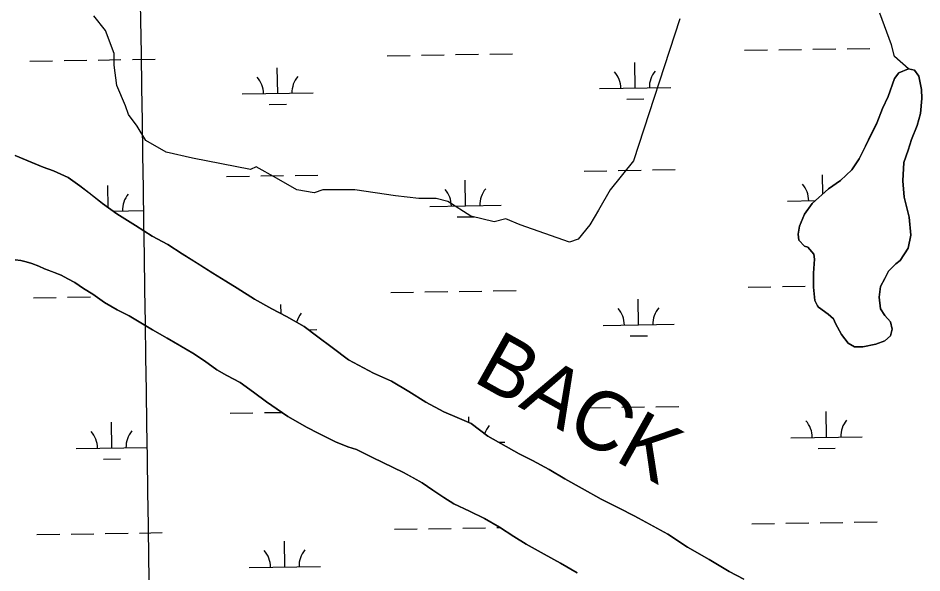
# Model space of a CAD drawing. Extents: x 3807117 to 3845308, y 337856 to 363736.
# Drawn here: x 3826910 to 3828179, y 355901 to 356681 of the extents above; entities that cross this region are included whole.
import ezdxf

# ---------------------------------------------------------------- set-up
doc = ezdxf.new("R2010")
doc.units = 0
for name, color, linetype in [('V-GRID-MAJR', 7, 'Continuous'), ('V-RIVR-IDEN', 7, 'Continuous'), ('V-TOPO-SHOR', 7, 'Continuous'), ('V-WETL-SWMP', 7, 'Continuous')]:
    doc.layers.add(name, color=color, linetype=linetype)

msp = doc.modelspace()

# ---------------------------------------------------------------- linework, layer by layer
at = {"layer": 'V-GRID-MAJR'}
msp.add_spline([(3827279.7490000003, 343519.83400000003), (3827189.006, 349576.481), (3827098.2120000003, 355636.598), (3827007.418, 361696.713), (3827007.366, 361700.18200000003)], degree=3, dxfattribs=at)
at = {"layer": 'V-TOPO-SHOR'}
for points in [[(3827839.4147388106, 356679.8381328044), (3827774.232319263, 356480.2169729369), (3827741.641109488, 356439.47796071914), (3827725.3455046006, 356410.9606521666), (3827713.1238009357, 356390.5911460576), (3827696.8281960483, 356370.2216399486), (3827684.606492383, 356366.14773872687), (3827615.350171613, 356390.5911460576), (3827594.9806655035, 356398.7389485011), (3827578.6850606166, 356394.6650472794), (3827546.0938508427, 356402.81284972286), (3827513.502641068, 356423.18235583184), (3827497.2070361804, 356427.25625705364), (3827472.76362885, 356427.25625705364), (3827440.172419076, 356431.3301582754), (3827383.1378019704, 356439.47796071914), (3827338.324888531, 356439.47796071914), (3827326.1031848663, 356435.40405949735), (3827301.659777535, 356439.47796071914), (3827273.142468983, 356455.7735656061), (3827244.62516043, 356472.0691704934), (3827236.4773579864, 356467.9952692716), (3827154.999333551, 356484.2908741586), (3827118.334222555, 356492.4386766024), (3827089.8169140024, 356508.7342814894), (3827077.5952103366, 356529.1037875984), (3827065.373506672, 356545.3993924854), (3827061.2996054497, 356557.6210961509), (3827049.0779017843, 356586.1384047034), (3827045.0040005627, 356614.65571325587), (3827045.0040005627, 356630.9513181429), (3827032.7822968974, 356663.54252791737), (3827016.48669201, 356683.9120340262)], [(3828160.716, 356609.613), (3828140.883429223, 356626.87741692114), (3828136.809528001, 356643.1730218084), (3828120.5139231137, 356687.9859352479)], [(3828047.919, 356265.02), (3828034.269, 356274.88300000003), (3828032.972, 356276.847), (3828029.098, 356284.04600000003), (3828027.242, 356302.982), (3828027.346, 356322.55700000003), (3828028.758, 356342.125), (3828027.492, 356349.31200000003), (3828019.062, 356359.14400000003), (3828014.501, 356360.47500000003), (3828006.717, 356368.999), (3828005.457, 356377.49), (3828007.475, 356388.574), (3828014.745, 356405.501), (3828025.268, 356420.451), (3828048.22, 356441.21), (3828065.2490000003, 356452.863), (3828080.99, 356467.787), (3828091.5160000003, 356483.39), (3828100.093, 356500.96400000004), (3828108.673, 356518.536), (3828115.931, 356533.507), (3828123.8710000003, 356553.692), (3828131.794, 356570.617), (3828141.068, 356596.016), (3828146.9820000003, 356603.815), (3828160.716, 356609.613), (3828169.191, 356607.61), (3828175.018, 356599.094), (3828178.833, 356580.80100000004), (3828179.415, 356567.74700000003), (3828177.344, 356546.878), (3828172.685, 356529.935), (3828164.7490000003, 356510.401), (3828160.1, 356495.418), (3828154.132, 356477.832), (3828152.688, 356452.39), (3828154.521, 356429.54), (3828161.548, 356401.444), (3828164.022, 356375.981), (3828160.008, 356357.729), (3828148.8170000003, 356340.172), (3828142.921, 356335.635), (3828132.423, 356325.252), (3828127.148, 356314.84), (3828121.214, 356303.777), (3828119.1750000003, 356288.779), (3828121.045, 356272.454), (3828127.52, 356263.286), (3828135.3030000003, 356254.106), (3828137.8540000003, 356243.651), (3828135.196, 356234.532), (3828127.326, 356227.39400000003), (3828114.903, 356222.895), (3828096.612, 356219.077), (3828084.865, 356219.143), (3828075.757, 356224.41000000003), (3828066.686, 356236.207), (3828058.288, 356251.913), (3828055.06, 356258.456), (3828047.919, 356265.02)], [(3826906.341, 356487.853), (3826929.688, 356477.97500000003), (3826945.644, 356471.25800000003), (3826960.048, 356466.109), (3826980.671, 356457.026), (3826996.987, 356445.238), (3827011.747, 356433.847), (3827028.838, 356420.492), (3827049.039, 356405.953), (3827075.0840000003, 356389.43), (3827098.404, 356374.484), (3827120.572, 356362.663), (3827140.784, 356349.68), (3827160.219, 356337.485), (3827183.931, 356322.534), (3827202.199, 356311.127), (3827217.752, 356301.681), (3827242.237, 356285.947), (3827266.347, 356272.555), (3827287.3510000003, 356261.52), (3827311.847, 356247.737), (3827331.27, 356233.2), (3827351.47, 356217.879), (3827374.3910000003, 356200.983), (3827409.3910000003, 356182.072), (3827434.682, 356170.626), (3827458.787, 356156.454), (3827482.886, 356141.112), (3827508.164, 356127.71400000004), (3827526.844, 356119.813), (3827546.3000000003, 356111.125), (3827569.995, 356093.447), (3827613.935, 356068.635), (3827632.6070000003, 356059.174), (3827655.94, 356046.566), (3827678.1010000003, 356033.576), (3827702.208, 356019.795), (3827729.043, 356005.217), (3827754.323, 355992.21), (3827775.328, 355981.565)], [(3826905.9620000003, 356341.21), (3826914.185, 356340.38300000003), (3826921.617, 356338.384), (3826929.436, 356335.992), (3826939.2090000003, 356332.414), (3826947.416, 356328.842), (3826957.58, 356324.871), (3826970.869, 356319.708), (3826980.2430000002, 356314.565), (3826990.006, 356309.42100000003), (3827002.103, 356301.129), (3827014.985, 356292.832), (3827031.375, 356281.386), (3827049.336, 356271.105), (3827066.132, 356262.397), (3827082.532, 356252.906), (3827098.931, 356243.025), (3827119.628, 356231.163), (3827137.198, 356220.884), (3827155.5500000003, 356210.208), (3827171.9420000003, 356199.15), (3827189.11, 356186.916), (3827203.559, 356178.61100000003), (3827221.913, 356168.719), (3827240.642, 356155.30100000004), (3827258.98, 356141.884), (3827272.6380000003, 356132.408), (3827289.028, 356120.962), (3827315.974, 356105.93200000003), (3827331.596, 356097.621), (3827355.815, 356085.347), (3827373.406, 356078.593), (3827385.526, 356074.612), (3827407.794, 356063.52400000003), (3827451.549, 356042.526), (3827462.875, 356036.197), (3827477.714, 356027.891), (3827492.542, 356017.628), (3827508.156, 356007.357), (3827522.2090000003, 355998.666), (3827544.088, 355988.362), (3827565.182, 355977.67100000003), (3827586.271, 355965.80700000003), (3827606.566, 355952.381), (3827623.7430000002, 355941.711), (3827649.128, 355927.864), (3827671.779, 355915.207), (3827695.2060000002, 355901.371)], [(3827775.328, 355981.565), (3827798.663, 355968.957), (3827822.774, 355955.957), (3827850.366, 355937.47500000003), (3827880.6950000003, 355920.14900000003), (3827908.6890000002, 355903.618), (3827929.301, 355892.583)]]:
    msp.add_lwpolyline(points, dxfattribs=at)
at = {"layer": 'V-WETL-SWMP'}
for p, q in [((3827428.6164234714, 356628.1019231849), (3827460.6128323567, 356628.58129977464)), ((3827476.6110367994, 356628.8209880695), (3827508.6074456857, 356629.3003646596)), ((3827524.6056501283, 356629.5400529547), (3827556.6020590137, 356630.0194295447)), ((3827572.6002634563, 356630.25911783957), (3827604.596672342, 356630.7384944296)), ((3827930.4680981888, 356635.6207652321), (3827962.4645070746, 356636.1001418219)), ((3827978.4627115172, 356636.3398301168), (3828010.459120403, 356636.8192067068)), ((3828026.4573248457, 356637.0588950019), (3828058.4537337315, 356637.5382715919)), ((3828074.451938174, 356637.7779598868), (3828106.44834706, 356638.2573364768)), ((3826926.7647487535, 356620.5830811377), (3826958.7611576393, 356621.06245772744)), ((3826974.759362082, 356621.3021460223), (3827006.7557709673, 356621.7815226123)), ((3827022.7539754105, 356622.0212109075), (3827054.750384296, 356622.5005874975)), ((3827070.748588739, 356622.74027579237), (3827102.7449976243, 356623.21965238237)), ((3827776.6535882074, 356582.56859091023), (3827776.11428963, 356618.5645511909)), ((3827274.8019134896, 356575.049748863), (3827274.262614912, 356611.0457091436)), ((3828146.9821931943, 356603.8139728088), (3828141.0671932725, 356596.0159727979)), ((3828160.7171929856, 356609.6129728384), (3828146.9821931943, 356603.8139728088)), ((3828169.1901928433, 356607.6099728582), (3828160.7171929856, 356609.6129728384)), ((3828175.01719273, 356599.09497287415), (3828169.1901928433, 356607.6099728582)), ((3828141.0671932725, 356596.0159727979), (3828131.7941933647, 356570.615972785)), ((3828178.833192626, 356580.8019728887), (3828175.0171927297, 356599.09497287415)), ((3827726.6591993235, 356581.8195649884), (3827826.6479770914, 356583.31761683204)), ((3828179.415192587, 356567.7479728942), (3828178.833192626, 356580.8019728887)), ((3827224.8075246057, 356574.3007229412), (3827324.796302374, 356575.79877478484)), ((3827764.8860992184, 356566.95955626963), (3827788.883405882, 356567.31908871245)), ((3828131.7941933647, 356570.615972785), (3828123.8711934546, 356553.6919727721)), ((3828177.344192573, 356546.8779728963), (3828179.415192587, 356567.7479728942)), ((3827263.0344245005, 356559.44071422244), (3827287.0317311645, 356559.80024666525)), ((3828123.8711934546, 356553.6919727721), (3828115.9311935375, 356533.5059727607)), ((3828172.6851926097, 356529.9359728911), (3828177.3441925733, 356546.8779728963)), ((3828115.9311935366, 356533.5059727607), (3828091.5161938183, 356483.39097272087)), ((3828164.7481926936, 356510.4019728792), (3828172.6851926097, 356529.9359728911)), ((3828160.099192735, 356495.4189728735), (3828164.7481926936, 356510.4019728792)), ((3826945.6442123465, 356471.2579701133), (3826906.340213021, 356487.8519700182)), ((3828154.1311927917, 356477.83197286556), (3828160.099192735, 356495.4189728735)), ((3828091.5161938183, 356483.39097272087), (3828080.9901939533, 356467.7869727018)), ((3828152.688192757, 356452.38997287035), (3828154.1311927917, 356477.83197286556)), ((3826960.047212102, 356466.1099701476), (3826945.6442123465, 356471.2579701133)), ((3826980.6702117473, 356457.0269701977), (3826960.047212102, 356466.1099701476)), ((3827704.983057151, 356466.04985414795), (3827736.979466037, 356466.52923073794)), ((3827752.9776704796, 356466.7689190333), (3827784.974079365, 356467.2482956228)), ((3827800.972283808, 356467.4879839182), (3827832.968692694, 356467.96736050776)), ((3828080.9901939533, 356467.7869727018), (3828065.248194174, 356452.86297267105)), ((3826996.9882114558, 356445.23797023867), (3826980.6702117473, 356457.0269701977)), ((3827203.131382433, 356458.5310121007), (3827235.127791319, 356459.01038869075)), ((3827251.125995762, 356459.2500769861), (3827283.1224046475, 356459.7294535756)), ((3827299.1206090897, 356459.96914187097), (3827331.117017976, 356460.4485184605)), ((3827538.633350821, 356417.1223589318), (3827538.0940522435, 356453.1183192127)), ((3828040.3435145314, 356434.08647829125), (3828039.9457269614, 356460.6371612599)), ((3828065.248194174, 356452.86297267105), (3828048.219194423, 356441.20897263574)), ((3828154.522192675, 356429.54097288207), (3828152.688192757, 356452.38997287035)), ((3827028.837210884, 356420.49297031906), (3826996.9882114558, 356445.23797023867)), ((3827036.703345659, 356414.8317516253), (3827036.2423775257, 356445.5994771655)), ((3828048.219194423, 356441.20897263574), (3828025.2671947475, 356420.45197259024)), ((3827990.490636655, 356423.8921750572), (3828029.7211024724, 356424.47993373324)), ((3828161.5481924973, 356401.4429729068), (3828154.522192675, 356429.54097288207)), ((3827049.0402105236, 356405.95297036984), (3827028.837210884, 356420.49297031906)), ((3827488.6389619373, 356416.37333300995), (3827588.6277397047, 356417.8713848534)), ((3828025.2671947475, 356420.45197259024), (3828014.7451948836, 356405.4999725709)), ((3827043.821311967, 356409.70898611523), (3827086.7760649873, 356410.3525428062)), ((3827075.083210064, 356389.42997043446), (3827049.0402105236, 356405.95297036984)), ((3827526.8658618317, 356401.5133242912), (3827550.863168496, 356401.8728567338)), ((3828014.7451948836, 356405.4999725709), (3828007.475194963, 356388.57297255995)), ((3828164.0211923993, 356375.9799729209), (3828161.5481924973, 356401.4429729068)), ((3827098.404209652, 356374.4829704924), (3827075.083210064, 356389.42997043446)), ((3828007.475194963, 356388.57297255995), (3828005.45819497, 356377.48997255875)), ((3827120.5722092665, 356362.6619705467), (3827098.404209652, 356374.4829704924)), ((3828005.45819497, 356377.48997255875), (3828006.7171949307, 356368.99997256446)), ((3828160.007192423, 356357.7299729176), (3828164.0211923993, 356375.9799729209)), ((3827140.7842089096, 356349.680970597), (3827120.5722092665, 356362.661970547)), ((3828006.717194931, 356368.99997256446), (3828014.5011947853, 356360.474972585)), ((3828014.5011947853, 356360.47497258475), (3828019.062194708, 356359.1449725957)), ((3827183.931208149, 356322.53497070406), (3827140.7842089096, 356349.680970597)), ((3828019.062194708, 356359.1449725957), (3828027.492194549, 356349.3109726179)), ((3828027.4921945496, 356349.3109726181), (3828028.758194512, 356342.12597262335)), ((3828148.8181925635, 356340.17097289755), (3828160.007192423, 356357.7299729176)), ((3826914.185001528, 356340.3820043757), (3826905.9630018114, 356341.21000518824)), ((3826921.616001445, 356338.38400413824), (3826914.185001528, 356340.3820043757)), ((3826929.4370013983, 356335.991004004), (3826921.616001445, 356338.38400413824)), ((3826939.210001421, 356332.41300407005), (3826929.4370013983, 356335.991004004)), ((3828028.758194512, 356342.12597262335), (3828027.347194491, 356322.5569726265)), ((3828132.4241927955, 356325.25097286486), (3828142.921192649, 356335.6349728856)), ((3828142.921192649, 356335.6349728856), (3828148.8181925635, 356340.17097289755)), ((3826947.416001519, 356328.84300435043), (3826939.210001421, 356332.4130040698)), ((3826970.8690016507, 356319.7070047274), (3826947.416001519, 356328.84300435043)), ((3827202.200207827, 356311.12597074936), (3827183.931208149, 356322.53497070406)), ((3828027.3471944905, 356322.5569726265), (3828027.2411944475, 356302.9809726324)), ((3828127.1471928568, 356314.83897285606), (3828132.4241927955, 356325.25097286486)), ((3826980.24200191, 356314.56500547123), (3826970.8690016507, 356319.7070047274)), ((3826990.0060021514, 356309.4200061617), (3826980.24200191, 356314.56500547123)), ((3827002.104002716, 356301.12800778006), (3826990.0060021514, 356309.42000616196)), ((3827217.751207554, 356301.68097078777), (3827202.200207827, 356311.12597074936)), ((3828121.214192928, 356303.7769728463), (3828127.1471928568, 356314.83897285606)), ((3827014.985003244, 356292.8330092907), (3827002.104002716, 356301.12800778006)), ((3827242.238207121, 356285.94697084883), (3827217.751207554, 356301.68097078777)), ((3827529.589293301, 356296.9023838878), (3827561.5857021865, 356297.3817604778)), ((3827577.5839066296, 356297.62144877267), (3827609.580315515, 356298.10082536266)), ((3827935.4517413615, 356302.9830961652), (3827967.448150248, 356303.46247275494)), ((3827983.4463546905, 356303.7021610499), (3828015.442763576, 356304.1815376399)), ((3828027.2411944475, 356302.9809726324), (3828029.0971943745, 356284.04597264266)), ((3828119.1751929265, 356288.77997284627), (3828121.214192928, 356303.7769728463)), ((3826931.749870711, 356287.9470563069), (3826963.746279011, 356288.426432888)), ((3826979.7444831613, 356288.6661211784), (3827011.740891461, 356289.1454977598)), ((3827031.3750040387, 356281.3850115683), (3827014.985003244, 356292.8330092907)), ((3827266.3472067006, 356272.5549709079), (3827242.238207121, 356285.94697084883)), ((3827433.600066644, 356295.464254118), (3827465.59647553, 356295.94363070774)), ((3827481.5946799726, 356296.1833190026), (3827513.5910888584, 356296.6626955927)), ((3827781.6372313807, 356249.9309218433), (3827781.0979328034, 356285.926882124)), ((3828029.0971943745, 356284.04597264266), (3828032.973194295, 356276.8469726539)), ((3828121.045192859, 356272.45497285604), (3828119.1751929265, 356288.77997284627)), ((3827049.337004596, 356271.10401316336), (3827031.3750040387, 356281.3850115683)), ((3827287.350206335, 356261.51997095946), (3827266.3472067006, 356272.5549709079)), ((3827279.4369882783, 356265.67758474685), (3827279.246258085, 356278.4080400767)), ((3828032.9731942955, 356276.8469726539), (3828034.2681942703, 356274.88297265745)), ((3828034.2681942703, 356274.88297265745), (3828047.918194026, 356265.0199726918)), ((3828127.5201927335, 356263.2849728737), (3828121.045192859, 356272.45497285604)), ((3827066.133004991, 356262.3960142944), (3827049.337004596, 356271.10401316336)), ((3827082.5330055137, 356252.90601579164), (3827066.133004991, 356262.3960142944)), ((3827311.847205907, 356247.73697101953), (3827287.350206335, 356261.51997095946)), ((3828047.918194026, 356265.0199726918), (3828055.060193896, 356258.45597271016)), ((3828135.3021925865, 356254.1069728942), (3828127.520192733, 356263.28497287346)), ((3827098.931006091, 356243.02501744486), (3827082.5330055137, 356252.90601579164)), ((3827331.270205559, 356233.19997106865), (3827311.847205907, 356247.73697101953)), ((3827731.6428424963, 356249.1818959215), (3827831.631620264, 356250.67994776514)), ((3828055.060193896, 356258.45597271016), (3828058.288193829, 356251.91297271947)), ((3828058.288193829, 356251.91297271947), (3828066.686193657, 356236.2059727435)), ((3828137.855192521, 356243.6519729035), (3828135.302192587, 356254.1069728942)), ((3827119.6270067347, 356231.1620192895), (3827098.931006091, 356243.02501744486)), ((3827318.193000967, 356242.9875077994), (3827329.7799455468, 356243.1611057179)), ((3827769.869742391, 356234.32188720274), (3827793.867049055, 356234.68141964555)), ((3828066.686193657, 356236.2059727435), (3828075.7581934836, 356224.4109727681)), ((3828127.3261926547, 356227.3949728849), (3828135.1961925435, 356234.5309729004)), ((3828135.1961925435, 356234.5309729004), (3828137.855192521, 356243.6519729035)), ((3827155.550007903, 356210.2080226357), (3827119.6270067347, 356231.1620192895)), ((3827351.4692051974, 356217.8799711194), (3827331.270205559, 356233.19997106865)), ((3828075.7581934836, 356224.4109727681), (3828084.865193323, 356219.1419727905)), ((3828096.6111931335, 356219.0779728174), (3828114.903192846, 356222.89397285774)), ((3828114.903192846, 356222.89397285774), (3828127.3261926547, 356227.3949728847)), ((3827171.941008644, 356199.15102475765), (3827155.550007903, 356210.2080226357)), ((3827374.3902047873, 356200.98397117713), (3827351.4692051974, 356217.8799711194)), ((3828084.865193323, 356219.1419727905), (3828096.6111931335, 356219.0779728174)), ((3827189.110009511, 356186.9160272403), (3827171.941008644, 356199.1510247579)), ((3827409.391204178, 356182.0729712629), (3827374.3902047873, 356200.98397117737)), ((3827203.5580099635, 356178.6120285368), (3827189.110009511, 356186.9160272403)), ((3827221.9140104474, 356168.7200299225), (3827203.5580099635, 356178.6120285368)), ((3827434.681203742, 356170.6249713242), (3827409.391204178, 356182.0729712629)), ((3827458.7862033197, 356156.4539713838), (3827434.681203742, 356170.6249713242)), ((3827240.643011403, 356155.3010326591), (3827221.9140104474, 356168.7200299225)), ((3827258.980012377, 356141.88403544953), (3827240.643011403, 356155.3010326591)), ((3827482.886202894, 356141.1119714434), (3827458.7862033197, 356156.4539713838)), ((3827289.0280138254, 356120.96203959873), (3827258.980012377, 356141.88403544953)), ((3827508.1652024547, 356127.7139715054), (3827482.886202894, 356141.1119714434)), ((3827709.9667003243, 356133.412185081), (3827741.96310921, 356133.89156167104)), ((3827757.9613136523, 356134.1312499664), (3827789.957722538, 356134.6106265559)), ((3827805.955926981, 356134.85031485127), (3827837.9523358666, 356135.32969144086)), ((3827208.116523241, 356125.8950202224), (3827240.1129315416, 356126.3743968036)), ((3827256.111135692, 356126.6140850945), (3827280.3882142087, 356126.97780913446)), ((3827315.9730146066, 356105.9310418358), (3827289.0280138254, 356120.96203959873)), ((3827526.844202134, 356119.8119715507), (3827508.1652024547, 356127.71397150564)), ((3827546.299201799, 356111.1259715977), (3827526.844202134, 356119.81197155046)), ((3827543.197098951, 356112.51095569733), (3827543.0776954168, 356120.4806501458)), ((3828045.468668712, 356092.0035319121), (3828044.9293701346, 356127.999492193)), ((3827041.7668266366, 356076.96753427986), (3827041.227522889, 356112.9634874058)), ((3827569.996201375, 356093.4459716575), (3827546.299201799, 356111.1259715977)), ((3827331.5960150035, 356097.6210429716), (3827315.9730146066, 356105.93104183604)), ((3827355.8150155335, 356085.34704449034), (3827331.5960150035, 356097.6210429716)), ((3827373.4050156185, 356078.59304473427), (3827355.8150155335, 356085.34704449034)), ((3827613.9352006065, 356068.6359717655), (3827569.996201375, 356093.4459716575)), ((3827584.774738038, 356085.10132340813), (3827593.6113828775, 356085.2337157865)), ((3827995.4742798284, 356091.25450599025), (3828095.4630575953, 356092.7525578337)), ((3826991.772438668, 356076.21850837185), (3827091.7612146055, 356077.7165601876)), ((3827385.526015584, 356074.61104463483), (3827373.4050156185, 356078.59304473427)), ((3827407.7930160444, 356063.523045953), (3827385.526015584, 356074.61104463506)), ((3827632.606200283, 356059.1739718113), (3827613.9352006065, 356068.6359717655)), ((3828033.701179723, 356076.39449727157), (3828057.6984863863, 356076.7540297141)), ((3827029.999340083, 356061.35850270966), (3827053.996646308, 356061.7180351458)), ((3827451.550016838, 356042.52604822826), (3827407.7930160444, 356063.5230459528)), ((3827655.9401998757, 356046.5669718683), (3827632.606200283, 356059.1739718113)), ((3827678.1011994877, 356033.5759719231), (3827655.9401998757, 356046.5669718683)), ((3827477.714017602, 356027.8910504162), (3827451.550016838, 356042.52604822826)), ((3827702.2091990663, 356019.7939719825), (3827678.1011994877, 356033.5759719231)), ((3827492.543018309, 356017.62705243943), (3827477.714017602, 356027.8910504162)), ((3827508.1560189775, 356007.3580543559), (3827492.543018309, 356017.62705243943)), ((3827729.042198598, 356005.21797204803), (3827702.2091990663, 356019.7939719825)), ((3827522.2100195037, 355998.6650558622), (3827508.1560189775, 356007.3580543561)), ((3827754.3241981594, 355992.20997211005), (3827729.042198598, 356005.21797204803)), ((3827544.0890198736, 355988.362056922), (3827522.2100195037, 355998.6650558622)), ((3827775.328197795, 355981.5649721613), (3827754.3241981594, 355992.20997211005)), ((3827565.183020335, 355977.67205824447), (3827544.0890198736, 355988.3620569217)), ((3827822.774196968, 355955.9559722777), (3827775.328197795, 355981.5649721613)), ((3827586.270020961, 355965.8070600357), (3827565.183020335, 355977.67205824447)), ((3827940.4353845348, 355970.3454270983), (3827972.4317934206, 355970.82480368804)), ((3827988.4299978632, 355971.0644919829), (3828020.426406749, 355971.543868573)), ((3828036.4246111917, 355971.7835568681), (3828068.421020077, 355972.2629334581)), ((3828084.41922452, 355972.50262175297), (3828116.4156334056, 355972.981998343)), ((3826936.733561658, 355955.3094533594), (3826968.729969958, 355955.78882994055)), ((3826984.728174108, 355956.02851823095), (3827016.724582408, 355956.5078948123)), ((3827032.7227865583, 355956.74758310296), (3827064.719194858, 355957.22695968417)), ((3827080.717399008, 355957.46664797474), (3827112.713807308, 355957.94602455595)), ((3827438.58522719, 355962.82829526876), (3827470.5816354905, 355963.30767184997)), ((3827486.5798396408, 355963.5473601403), (3827518.5762479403, 355964.02673672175)), ((3827534.5744520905, 355964.2664250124), (3827566.57086039, 355964.7458015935)), ((3827582.5690645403, 355964.98548988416), (3827587.40243084, 355965.0579043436)), ((3827606.5660218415, 355952.38006255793), (3827586.270020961, 355965.8070600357)), ((3827850.367196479, 355937.47497234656), (3827822.774196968, 355955.9559722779)), ((3827284.7707273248, 355909.7761310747), (3827284.2314235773, 355945.7720842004)), ((3827623.7430224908, 355941.7110644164), (3827606.5660218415, 355952.38006255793)), ((3827649.1280231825, 355927.8640663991), (3827623.7430224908, 355941.7110644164)), ((3827880.696195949, 355920.1499724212), (3827850.367196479, 355937.47497234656)), ((3827671.778023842, 355915.2070682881), (3827649.1280231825, 355927.8640663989)), ((3827908.6891954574, 355903.61697249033), (3827880.696195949, 355920.1499724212)), ((3827234.776339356, 355909.02710516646), (3827334.7651152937, 355910.52515698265)), ((3827695.205024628, 355901.3710705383), (3827671.778023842, 355915.20706828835)), ((3827929.3011950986, 355892.58397254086), (3827908.6891954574, 355903.61697249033))]:
    msp.add_line(p, q, dxfattribs=at)
for centre, radius, start, end in [((3827721.409738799, 356582.2157729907), 35.246287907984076, 0.08653252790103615, 41.63019086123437), ((3827831.8832120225, 356583.8709086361), 35.246287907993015, 140.0865295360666, 181.63018786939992), ((3827219.5580640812, 356574.6969309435), 35.246287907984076, 0.08653252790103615, 41.63019086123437), ((3827330.031537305, 356576.3520665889), 35.246287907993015, 140.0865295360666, 181.63018786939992), ((3827483.3895014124, 356416.7695410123), 35.246287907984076, 0.08653252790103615, 41.63019086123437), ((3827593.862974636, 356418.4246766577), 35.246287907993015, 140.0865295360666, 181.63018786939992), ((3827985.24117613, 356424.2883830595), 35.246287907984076, 0.08653252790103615, 41.63019086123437), ((3827092.0112999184, 356410.90583461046), 35.246287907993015, 140.0865295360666, 181.63018786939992), ((3827726.393381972, 356249.5781039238), 35.246287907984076, 0.08653252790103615, 41.63019086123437), ((3827836.8668551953, 356251.2332395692), 35.246287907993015, 140.0865295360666, 181.63018786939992), ((3827335.015180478, 356243.714397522), 35.246287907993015, 140.08652953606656, 163.51280629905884), ((3827598.8466178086, 356085.78700759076), 35.246287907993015, 140.08652953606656, 161.65356151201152), ((3827990.2248193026, 356091.6507139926), 35.246287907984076, 0.08653252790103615, 41.63019086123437), ((3828100.6982925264, 356093.305849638), 35.246287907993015, 140.0865295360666, 181.63018786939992), ((3826986.5229781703, 356076.6147162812), 35.24628790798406, 0.08653266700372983, 41.630191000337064), ((3827096.9964493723, 356078.2698518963), 35.24628790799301, 140.0865294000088, 181.63018773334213), ((3827229.526878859, 355909.423313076), 35.24628790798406, 0.08653266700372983, 41.630191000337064), ((3827340.0003500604, 355911.0784486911), 35.24628790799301, 140.0865294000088, 181.63018773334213)]:
    msp.add_arc(centre, radius, start, end, dxfattribs=at)

# ---------------------------------------------------------------- texts
at = {"layer": 'V-RIVR-IDEN'}
msp.add_text('BACK', height=82.99983200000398, rotation=330.7807920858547, dxfattribs=at).set_placement((3827546.9578666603, 356171.61963122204))

doc.saveas('drawing.dxf')
